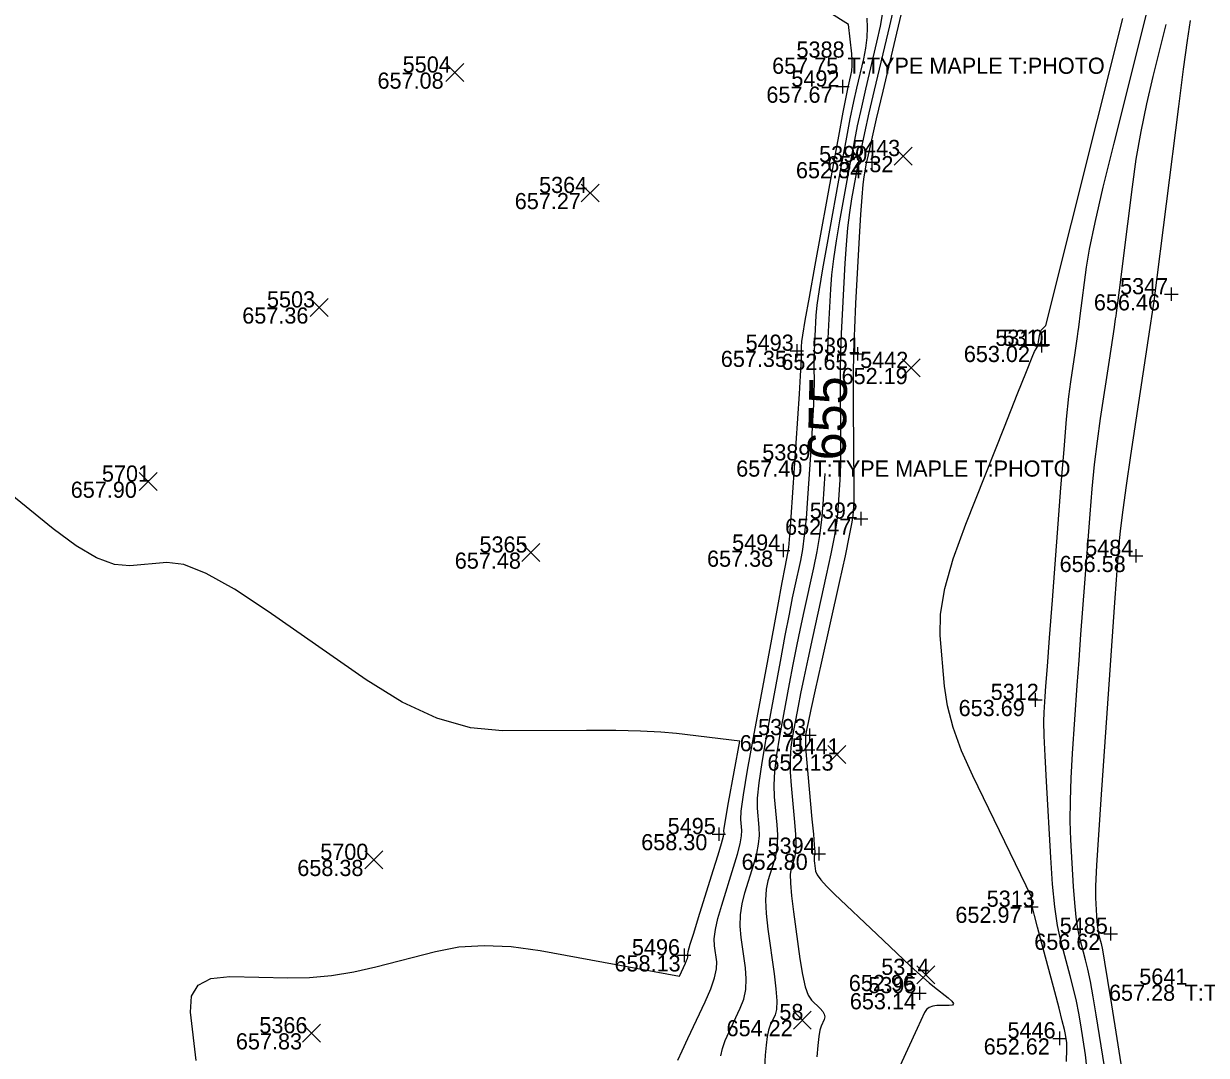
# Model space of a CAD drawing. Extents: x 2129350 to 2137777, y 657588 to 659885.
# Drawn here: x 2132684.7 to 2132772.5, y 657991.9 to 658068.5 of the extents above; entities that cross this region are included whole.
import ezdxf

# ---------------------------------------------------------------- set-up
doc = ezdxf.new("R2010")
doc.units = 0
for name, color, linetype in [('DT_X_Contour_Major', 7, 'Continuous'), ('DT_X_Contour_Minor', 7, 'Continuous'), ('SV_X_Random_Point', 7, 'Continuous'), ('SV_X_Shot_Marker', 7, 'Continuous'), ('SV_X_Text_Comment', 7, 'Continuous'), ('SV_X_Text_Elevation', 7, 'Continuous'), ('SV_X_Text_Name', 7, 'Continuous')]:
    doc.layers.add(name, color=color, linetype=linetype)

msp = doc.modelspace()

# ---------------------------------------------------------------- linework, layer by layer
at = {"layer": 'DT_X_Contour_Major'}
for points in [[(2132748.43, 658069.372), (2132748.256, 658068.368), (2132747.991, 658067.163), (2132747.166, 658063.677), (2132746.86, 658062.342), (2132746.561, 658060.948), (2132746.27, 658059.498), (2132745.986, 658057.99), (2132745.239, 658053.892), (2132744.987, 658052.422), (2132744.791, 658051.086), (2132744.652, 658049.884), (2132744.569, 658048.816), (2132744.424, 658046.144), (2132744.377, 658045.157), (2132744.345, 658044.2), (2132744.334, 658043.526)], [(2132764.903, 657991.096), (2132764.29, 657994.937), (2132764.068, 657996.273), (2132763.864, 657997.4), (2132763.678, 657998.318), (2132763.508, 657999.027), (2132763.08, 658000.638), (2132762.93, 658001.33), (2132762.802, 658002.198), (2132762.696, 658003.241), (2132762.612, 658004.46), (2132762.417, 658007.943), (2132762.37, 658009.322), (2132762.374, 658010.848), (2132762.429, 658012.52), (2132762.536, 658014.339), (2132762.89, 658019.384), (2132763.024, 658021.279), (2132763.162, 658023.181), (2132763.303, 658025.089), (2132763.447, 658027.003), (2132763.835, 658032.116), (2132763.993, 658033.997), (2132764.176, 658035.807), (2132764.384, 658037.545), (2132764.618, 658039.211), (2132765.273, 658043.558), (2132765.642, 658046.004), (2132765.734, 658046.615), (2132765.764, 658046.819), (2132765.764, 658046.82), (2132765.797, 658047.077), (2132766.057, 658049.135), (2132766.284, 658050.936), (2132766.978, 658056.425), (2132767.269, 658058.482), (2132767.624, 658060.535), (2132768.042, 658062.586), (2132768.522, 658064.633), (2132769.483, 658068.472)], [(2132744.155, 658035.131), (2132744.005, 658032.866), (2132743.904, 658031.705), (2132743.755, 658030.527), (2132743.557, 658029.334), (2132743.311, 658028.124), (2132742.588, 658024.877), (2132742.318, 658023.628), (2132742.047, 658022.319), (2132741.777, 658020.949), (2132741.508, 658019.517), (2132740.789, 658015.619), (2132740.562, 658014.242), (2132740.421, 658013.036), (2132740.365, 658011.999), (2132740.395, 658011.132), (2132740.59, 658009.046), (2132740.632, 658008.293), (2132740.612, 658007.596), (2132740.531, 658006.957), (2132740.388, 658006.374), (2132739.925, 658004.897), (2132739.794, 658004.257), (2132739.751, 658003.445), (2132739.794, 658002.46), (2132739.924, 658001.303), (2132740.386, 657997.988), (2132740.521, 657996.864), (2132740.578, 657995.98), (2132740.558, 657995.334), (2132740.46, 657994.927), (2132740.097, 657994.162), (2132739.972, 657993.807), (2132739.869, 657993.317), (2132739.789, 657992.692), (2132739.732, 657991.931), (2132739.608, 657989.723)]]:
    msp.add_lwpolyline(points, dxfattribs=at)
at = {"layer": 'DT_X_Contour_Minor'}
for points in [[(2132733.242, 657991.572), (2132733.549, 657992.262), (2132733.976, 657993.176), (2132735.274, 657995.91), (2132735.691, 657996.863), (2132735.972, 657997.673), (2132736.115, 657998.339), (2132736.121, 657998.86), (2132735.954, 658000.06), (2132735.941, 658000.586), (2132736.026, 658001.264), (2132736.21, 658002.093), (2132736.492, 658003.075), (2132737.377, 658005.896), (2132737.664, 658006.86), (2132737.861, 658007.637), (2132737.967, 658008.227), (2132737.983, 658008.629), (2132737.907, 658009.452), (2132737.945, 658010.064), (2132738.116, 658011.283), (2132738.42, 658013.109), (2132738.858, 658015.542), (2132740.204, 658022.839), (2132740.651, 658025.257), (2132740.982, 658027.039), (2132741.198, 658028.186), (2132741.299, 658028.696), (2132741.413, 658029.209), (2132741.467, 658029.635), (2132741.545, 658030.529), (2132741.647, 658031.892), (2132741.772, 658033.722), (2132742.137, 658039.227), (2132742.257, 658041.05), (2132742.342, 658042.389), (2132742.393, 658043.246), (2132742.409, 658043.619), (2132742.406, 658043.971), (2132742.406, 658044.106), (2132742.409, 658044.244), (2132742.414, 658044.387), (2132742.421, 658044.535), (2132742.442, 658044.933), (2132742.511, 658045.4), (2132742.7, 658046.503), (2132743.009, 658048.24), (2132743.439, 658050.612), (2132744.747, 658057.785), (2132745.186, 658060.18), (2132745.522, 658061.984), (2132745.754, 658063.198), (2132745.884, 658063.822), (2132746.091, 658064.699), (2132746.153, 658065.045), (2132746.183, 658065.427), (2132746.182, 658065.844), (2132746.148, 658066.296), (2132745.917, 658068.488), (2132737.15, 658073.995)], [(2132749.31, 658070.003), (2132748.941, 658068.395), (2132747.807, 658063.605), (2132747.412, 658061.913), (2132747.081, 658060.431), (2132746.812, 658059.157), (2132746.606, 658058.092), (2132746.139, 658055.532), (2132745.976, 658054.514), (2132745.837, 658053.378), (2132745.723, 658052.126), (2132745.633, 658050.757), (2132745.425, 658046.949), (2132745.359, 658045.543), (2132745.314, 658044.178), (2132745.291, 658042.855), (2132745.29, 658041.574), (2132745.317, 658038.213), (2132745.32, 658037.024), (2132745.309, 658035.975), (2132745.284, 658035.066), (2132745.245, 658034.298), (2132745.122, 658032.438), (2132745.033, 658031.611), (2132744.86, 658030.527), (2132744.602, 658029.183), (2132744.259, 658027.582), (2132743.233, 658022.967), (2132742.878, 658021.35), (2132742.58, 658019.959), (2132742.341, 658018.795), (2132742.16, 658017.857), (2132741.754, 658015.658), (2132741.633, 658014.809), (2132741.573, 658013.912), (2132741.576, 658012.966), (2132741.64, 658011.971), (2132741.893, 658009.255), (2132741.964, 658008.326), (2132741.988, 658007.576), (2132741.964, 658007.005), (2132741.893, 658006.614), (2132741.641, 658005.809), (2132741.581, 658005.381), (2132741.59, 658004.701), (2132741.669, 658003.77), (2132741.817, 658002.586), (2132742.303, 657999.095), (2132742.493, 657997.921), (2132742.698, 657997.017), (2132742.916, 657996.384), (2132743.15, 657996.021), (2132743.791, 657995.413), (2132743.991, 657995.19), (2132744.109, 657994.977), (2132744.145, 657994.775), (2132744.099, 657994.582), (2132743.868, 657994.081), (2132743.783, 657993.798), (2132743.703, 657993.324), (2132743.627, 657992.659), (2132743.556, 657991.804)], [(2132749.891, 658069.627), (2132748.448, 658063.532), (2132747.965, 658061.485), (2132747.601, 658059.913), (2132747.354, 658058.816), (2132747.225, 658058.195), (2132747.039, 658057.172), (2132746.965, 658056.605), (2132746.883, 658055.67), (2132746.794, 658054.368), (2132746.697, 658052.698), (2132746.427, 658047.754), (2132746.34, 658045.928), (2132746.282, 658044.156), (2132746.252, 658042.438), (2132746.251, 658040.774), (2132746.287, 658036.411), (2132746.296, 658034.95), (2132746.298, 658033.836), (2132746.293, 658033.072), (2132746.281, 658032.655), (2132746.238, 658032.01), (2132746.162, 658031.518), (2132745.965, 658030.526), (2132745.647, 658029.033), (2132745.208, 658027.04), (2132743.878, 658021.058), (2132743.437, 658019.071), (2132743.113, 658017.599), (2132742.904, 658016.641), (2132742.811, 658016.196), (2132742.719, 658015.697), (2132742.704, 658015.376), (2132742.726, 658014.788), (2132742.786, 658013.933), (2132742.884, 658012.811), (2132743.196, 658009.463), (2132743.297, 658008.359), (2132743.364, 658007.555), (2132743.398, 658007.053), (2132743.399, 658006.853), (2132743.357, 658006.72), (2132743.347, 658006.649), (2132743.349, 658006.537), (2132743.362, 658006.383), (2132743.386, 658006.187), (2132743.467, 658005.61), (2132743.577, 658005.341), (2132743.849, 658004.966), (2132744.281, 658004.486), (2132744.874, 658003.901), (2132748.018, 658000.922), (2132750.481, 657998.586), (2132750.99, 657998.112), (2132751.461, 657997.688), (2132751.894, 657997.316), (2132752.289, 657996.996), (2132753.293, 657996.209), (2132753.58, 657995.951), (2132753.689, 657995.767), (2132753.619, 657995.656), (2132753.37, 657995.619), (2132752.468, 657995.618), (2132752.157, 657995.586), (2132751.902, 657995.49), (2132751.702, 657995.33), (2132751.558, 657995.106), (2132751.014, 657993.912), (2132749.726, 657991.123)], [(2132736.422, 657991.899), (2132736.556, 657992.444), (2132736.761, 657993.034), (2132737.036, 657993.669), (2132737.867, 657995.419), (2132738.125, 657996.099), (2132738.275, 657996.826), (2132738.318, 657997.601), (2132738.254, 657998.424), (2132737.939, 658000.682), (2132737.867, 658001.523), (2132737.888, 658002.354), (2132738.002, 658003.175), (2132738.208, 658003.986), (2132738.883, 658006.135), (2132739.097, 658006.908), (2132739.236, 658007.617), (2132739.299, 658008.26), (2132739.287, 658008.838), (2132739.151, 658010.292), (2132739.155, 658011.031), (2132739.268, 658012.159), (2132739.491, 658013.676), (2132739.824, 658015.581), (2132740.856, 658021.178), (2132741.214, 658023.103), (2132741.515, 658024.679), (2132741.758, 658025.907), (2132741.944, 658026.786), (2132742.362, 658028.666), (2132742.512, 658029.484), (2132742.65, 658030.528), (2132742.776, 658031.798), (2132742.889, 658033.294), (2132743.173, 658037.584), (2132743.266, 658039.055), (2132743.331, 658040.251), (2132743.369, 658041.172), (2132743.379, 658041.817), (2132743.368, 658043.172), (2132743.368, 658043.689), (2132743.377, 658044.222), (2132743.395, 658044.772), (2132743.422, 658045.339), (2132743.506, 658046.874), (2132743.582, 658047.642), (2132743.746, 658048.795), (2132743.998, 658050.331), (2132744.339, 658052.252), (2132745.367, 658057.888), (2132745.728, 658059.839), (2132746.041, 658061.466), (2132746.307, 658062.77), (2132746.525, 658063.75), (2132747.041, 658065.931), (2132747.202, 658066.734), (2132747.295, 658067.507), (2132747.322, 658068.251), (2132747.281, 658068.965)], [(2132762.089, 657991.476), (2132762.119, 657992.394), (2132762.105, 657992.853), (2132762.007, 657993.468), (2132761.93, 657993.839), (2132761.772, 657994.49), (2132761.533, 657995.421), (2132761.214, 657996.633), (2132760.255, 658000.238), (2132759.94, 658001.435), (2132759.713, 658002.323), (2132759.574, 658002.901), (2132759.524, 658003.17), (2132759.494, 658003.701), (2132755.136, 658012.684), (2132754.304, 658014.544), (2132753.674, 658016.276), (2132753.248, 658017.879), (2132753.024, 658019.353), (2132752.697, 658023.113), (2132752.725, 658024.687), (2132753.052, 658026.586), (2132753.678, 658028.812), (2132754.605, 658031.365), (2132757.474, 658038.607), (2132758.422, 658040.993), (2132759.112, 658042.72), (2132759.545, 658043.788), (2132759.72, 658044.196), (2132759.844, 658044.407), (2132759.915, 658044.526), (2132759.933, 658044.556), (2132759.94, 658044.567), (2132759.944, 658044.568), (2132759.949, 658044.591), (2132759.98, 658044.767), (2132760.007, 658044.921), (2132760.087, 658045.389), (2132760.121, 658045.549), (2132760.163, 658045.68), (2132760.214, 658045.781), (2132760.272, 658045.853), (2132760.561, 658046.117), (2132766.27, 658068.924)], [(2132763.607, 657991.049), (2132763.504, 657991.974), (2132763.148, 657994.202), (2132762.999, 657995.056), (2132762.818, 657995.945), (2132762.606, 657996.869), (2132762.361, 657997.83), (2132761.668, 658000.438), (2132761.425, 658001.558), (2132761.218, 658002.962), (2132761.047, 658004.65), (2132760.911, 658006.622), (2132760.595, 658012.26), (2132760.496, 658014.165), (2132760.434, 658015.654), (2132760.409, 658016.726), (2132760.421, 658017.381), (2132760.505, 658018.572), (2132760.562, 658019.354), (2132760.671, 658020.807), (2132760.831, 658022.932), (2132761.043, 658025.727), (2132761.677, 658034.076), (2132761.901, 658036.916), (2132762.095, 658039.175), (2132762.26, 658040.852), (2132762.396, 658041.947), (2132762.719, 658044.093), (2132762.825, 658044.798), (2132762.901, 658045.301), (2132762.962, 658045.704), (2132762.962, 658045.704), (2132762.978, 658045.832), (2132763.026, 658046.213), (2132763.106, 658046.849), (2132763.561, 658050.449), (2132763.786, 658051.788), (2132764.203, 658053.771), (2132764.814, 658056.398), (2132765.617, 658059.67), (2132768.015, 658069.252)], [(2132771.269, 658068.773), (2132771.045, 658067.299), (2132770.753, 658065.175), (2132770.395, 658062.401), (2132768.567, 658047.935), (2132768.151, 658045.172), (2132766.84, 658036.475), (2132766.509, 658034.238), (2132766.258, 658032.439), (2132766.086, 658031.079), (2132765.993, 658030.156), (2132765.85, 658028.279), (2132765.774, 658027.246), (2132765.653, 658025.555), (2132765.275, 658020.197), (2132764.651, 658011.297), (2132764.45, 658008.315), (2132764.314, 658006.042), (2132764.244, 658004.479), (2132764.239, 658003.626), (2132764.313, 658002.297), (2132764.345, 658001.832), (2132764.386, 658001.434), (2132764.435, 658001.103), (2132764.492, 658000.838), (2132764.655, 658000.224), (2132764.75, 657999.766), (2132764.911, 657998.855), (2132765.138, 657997.49), (2132765.431, 657995.671), (2132766.302, 657990.217)], [(2132697.493, 657991.548), (2132697.068, 657995.139), (2132697.13, 657996.313), (2132697.636, 657997.143), (2132698.586, 657997.63), (2132699.978, 657997.772), (2132704.284, 657997.691), (2132705.904, 657997.719), (2132707.535, 657997.862), (2132709.178, 657998.121), (2132710.832, 657998.496), (2132715.257, 657999.648), (2132716.986, 657999.976), (2132718.854, 658000.094), (2132720.861, 658000.004), (2132723.008, 657999.704), (2132733.351, 657997.816), (2132733.808, 657998.778), (2132733.893, 657998.965), (2132733.951, 657999.114), (2132733.983, 657999.224), (2132733.989, 657999.297), (2132733.969, 657999.438), (2132734.014, 657999.649), (2132734.163, 658000.173), (2132734.417, 658001.011), (2132734.776, 658002.164), (2132735.872, 658005.657), (2132736.23, 658006.812), (2132736.485, 658007.658), (2132736.635, 658008.194), (2132736.68, 658008.42), (2132736.662, 658008.612), (2132736.679, 658008.797), (2132736.742, 658009.207), (2132736.852, 658009.843), (2132737.008, 658010.703), (2132737.846, 658015.247), (2132733.147, 658015.824), (2132731.974, 658015.931), (2132730.468, 658016.005), (2132728.63, 658016.045), (2132726.459, 658016.052), (2132720.225, 658016.026), (2132717.839, 658016.256), (2132715.357, 658016.964), (2132712.778, 658018.152), (2132710.103, 658019.819), (2132702.84, 658024.901), (2132700.327, 658026.557), (2132698.236, 658027.714), (2132696.567, 658028.371), (2132695.32, 658028.528), (2132692.556, 658028.281), (2132691.424, 658028.383), (2132690.099, 658028.876), (2132688.581, 658029.758), (2132686.871, 658031.03), (2132682.055, 658034.941)]]:
    msp.add_lwpolyline(points, dxfattribs=at)
at = {"layer": 'SV_X_Random_Point'}
for p, q in [((2132716.024, 658064.248), (2132717.358, 658065.583)), ((2132716.024, 658065.583), (2132717.358, 658064.248)), ((2132749.293, 658058.046), (2132750.627, 658059.38)), ((2132749.293, 658059.38), (2132750.627, 658058.046)), ((2132726.071, 658055.301), (2132727.405, 658056.637)), ((2132726.071, 658056.637), (2132727.405, 658055.301)), ((2132705.96, 658046.802), (2132707.294, 658048.137)), ((2132705.96, 658048.137), (2132707.294, 658046.802)), ((2132749.882, 658042.307), (2132751.216, 658043.642)), ((2132749.882, 658043.642), (2132751.216, 658042.307)), ((2132693.257, 658033.865), (2132694.591, 658035.201)), ((2132693.257, 658035.201), (2132694.591, 658033.865)), ((2132721.657, 658028.6), (2132722.991, 658029.936)), ((2132721.657, 658029.936), (2132722.991, 658028.6)), ((2132744.372, 658013.602), (2132745.706, 658014.938)), ((2132744.372, 658014.938), (2132745.706, 658013.602)), ((2132709.998, 658005.775), (2132711.332, 658007.11)), ((2132709.998, 658007.11), (2132711.332, 658005.775)), ((2132750.977, 657997.233), (2132752.311, 657998.568)), ((2132750.977, 657998.568), (2132752.311, 657997.233)), ((2132741.811, 657993.877), (2132743.145, 657995.213)), ((2132741.811, 657995.213), (2132743.145, 657993.877)), ((2132705.392, 657992.899), (2132706.726, 657994.233)), ((2132705.392, 657994.233), (2132706.726, 657992.899))]:
    msp.add_line(p, q, dxfattribs=at)
at = {"layer": 'SV_X_Shot_Marker'}
for p, q in [((2132745.453, 658064.371), (2132745.453, 658063.371)), ((2132744.953, 658063.871), (2132745.953, 658063.871)), ((2132745.453, 658063.871), (2132745.453, 658063.871)), ((2132747.137, 658058.263), (2132748.137, 658058.263)), ((2132747.637, 658058.763), (2132747.637, 658057.763)), ((2132747.637, 658058.263), (2132747.637, 658058.263)), ((2132769.362, 658048.45), (2132770.362, 658048.45)), ((2132769.862, 658048.95), (2132769.862, 658047.95)), ((2132769.862, 658048.45), (2132769.862, 658048.45)), ((2132760.226, 658045.117), (2132760.226, 658044.117)), ((2132760.229, 658045.115), (2132760.229, 658044.115)), ((2132741.569, 658044.252), (2132742.569, 658044.252)), ((2132742.069, 658044.752), (2132742.069, 658043.752)), ((2132742.069, 658044.252), (2132742.069, 658044.252)), ((2132746.063, 658044.03), (2132747.063, 658044.03)), ((2132746.563, 658044.53), (2132746.563, 658043.53)), ((2132746.563, 658044.03), (2132746.563, 658044.03)), ((2132759.726, 658044.617), (2132760.726, 658044.617)), ((2132759.729, 658044.615), (2132760.729, 658044.615)), ((2132760.226, 658044.617), (2132760.226, 658044.617)), ((2132760.229, 658044.615), (2132760.229, 658044.615)), ((2132746.331, 658031.783), (2132747.331, 658031.783)), ((2132746.831, 658032.283), (2132746.831, 658031.283)), ((2132746.831, 658031.783), (2132746.831, 658031.783)), ((2132740.557, 658029.412), (2132741.557, 658029.412)), ((2132741.057, 658029.912), (2132741.057, 658028.912)), ((2132741.057, 658029.412), (2132741.057, 658029.412)), ((2132767.244, 658029.519), (2132767.244, 658028.519)), ((2132766.744, 658029.019), (2132767.744, 658029.019)), ((2132767.244, 658029.019), (2132767.244, 658029.019)), ((2132759.768, 658018.821), (2132759.768, 658017.821)), ((2132759.268, 658018.321), (2132760.268, 658018.321)), ((2132759.768, 658018.321), (2132759.768, 658018.321)), ((2132743.003, 658016.208), (2132743.003, 658015.208)), ((2132742.503, 658015.708), (2132743.503, 658015.708)), ((2132743.003, 658015.708), (2132743.003, 658015.708)), ((2132735.784, 658008.357), (2132736.784, 658008.357)), ((2132736.284, 658008.857), (2132736.284, 658007.857)), ((2132736.284, 658008.357), (2132736.284, 658008.357)), ((2132743.697, 658007.4), (2132743.697, 658006.4)), ((2132743.197, 658006.9), (2132744.197, 658006.9)), ((2132743.697, 658006.9), (2132743.697, 658006.9)), ((2132758.98, 658002.961), (2132759.98, 658002.961)), ((2132759.48, 658003.461), (2132759.48, 658002.461)), ((2132759.48, 658002.961), (2132759.48, 658002.961)), ((2132765.363, 658001.462), (2132765.363, 658000.462)), ((2132764.863, 658000.962), (2132765.863, 658000.962)), ((2132765.363, 658000.962), (2132765.363, 658000.962)), ((2132733.203, 657999.355), (2132734.203, 657999.355)), ((2132733.703, 657999.855), (2132733.703, 657998.855)), ((2132733.703, 657999.355), (2132733.703, 657999.355)), ((2132751.182, 657997.045), (2132751.182, 657996.045)), ((2132750.682, 657996.545), (2132751.682, 657996.545)), ((2132751.182, 657996.545), (2132751.182, 657996.545)), ((2132761.072, 657993.188), (2132762.072, 657993.188)), ((2132761.572, 657993.688), (2132761.572, 657992.688)), ((2132761.572, 657993.188), (2132761.572, 657993.188))]:
    msp.add_line(p, q, dxfattribs=at)

# ---------------------------------------------------------------- texts
at = {"layer": 'DT_X_Contour_Major'}
msp.add_text('655', height=2.8, rotation=88.78295, dxfattribs=at).set_placement((2132745.677, 658036.09))
at = {"layer": 'SV_X_Text_Comment'}
for p in [(2132745.842, 658064.822), (2132743.303, 658034.904), (2132770.853, 657995.975)]:
    msp.add_text('T:TYPE MAPLE T:PHOTO', height=1.2, dxfattribs=at).set_placement(p)
at = {"layer": 'SV_X_Text_Elevation'}
for s, p in [('657.75', (2132740.239, 658064.822)), ('657.08', (2132710.946, 658063.716)), ('657.67', (2132739.812, 658062.671)), ('652.34', (2132742.006, 658057.063)), ('652.32', (2132744.329, 658057.513)), ('657.27', (2132721.135, 658054.769)), ('656.46', (2132764.118, 658047.25)), ('657.36', (2132700.911, 658046.27)), ('657.35', (2132736.428, 658043.052)), ('652.65', (2132740.922, 658042.83)), ('653.02', (2132754.463, 658043.417)), ('653.02', (2132754.466, 658043.415)), ('652.19', (2132745.391, 658041.775)), ('657.40', (2132737.568, 658034.904)), ('657.90', (2132688.179, 658033.333)), ('652.47', (2132741.2, 658030.583)), ('657.48', (2132716.683, 658028.068)), ('657.38', (2132735.407, 658028.212)), ('656.58', (2132761.575, 658027.819)), ('653.69', (2132754.08, 658017.121)), ('652.71', (2132737.834, 658014.508)), ('652.13', (2132739.89, 658013.07)), ('658.30', (2132730.521, 658007.157)), ('658.38', (2132704.996, 658005.243)), ('652.80', (2132737.971, 658005.7)), ('652.97', (2132753.839, 658001.761)), ('656.62', (2132759.694, 657999.762)), ('658.13', (2132728.535, 657998.155)), ('652.96', (2132745.928, 657996.701)), ('657.28', (2132765.241, 657995.975)), ('653.14', (2132746.005, 657995.345)), ('654.22', (2132736.856, 657993.345)), ('657.83', (2132700.437, 657992.366)), ('652.62', (2132755.941, 657991.988))]:
    msp.add_text(s, height=1.2, dxfattribs=at).set_placement(p)
at = {"layer": 'SV_X_Text_Name'}
for s, p in [('5388', (2132742.044, 658066.022)), ('5504', (2132712.817, 658064.916)), ('5492', (2132741.664, 658063.871)), ('5443', (2132746.171, 658058.713)), ('5390', (2132743.725, 658058.263)), ('5364', (2132722.94, 658055.969)), ('5347', (2132766.064, 658048.45)), ('5503', (2132702.744, 658047.47)), ('5310', (2132756.806, 658044.617)), ('5311', (2132757.347, 658044.615)), ('5493', (2132738.271, 658044.252)), ('5391', (2132743.189, 658044.03)), ('5442', (2132746.77, 658042.975)), ('5389', (2132739.505, 658036.104)), ('5701', (2132690.494, 658034.533)), ('5392', (2132743.033, 658031.783)), ('5365', (2132718.516, 658029.268)), ('5494', (2132737.268, 658029.412)), ('5484', (2132763.474, 658029.019)), ('5312', (2132756.462, 658018.321)), ('5393', (2132739.195, 658015.708)), ('5441', (2132741.684, 658014.27)), ('5495', (2132732.486, 658008.357)), ('5394', (2132739.899, 658006.9)), ('5700', (2132706.697, 658006.443)), ('5313', (2132756.164, 658002.961)), ('5485', (2132761.584, 658000.962)), ('5496', (2132729.829, 657999.355)), ('5314', (2132748.338, 657997.901)), ('5641', (2132767.489, 657997.175)), ('5395', (2132747.374, 657996.545)), ('58', (2132740.777, 657994.545)), ('5366', (2132702.176, 657993.566)), ('5446', (2132757.708, 657993.188))]:
    msp.add_text(s, height=1.2, dxfattribs=at).set_placement(p)

doc.saveas('drawing.dxf')
